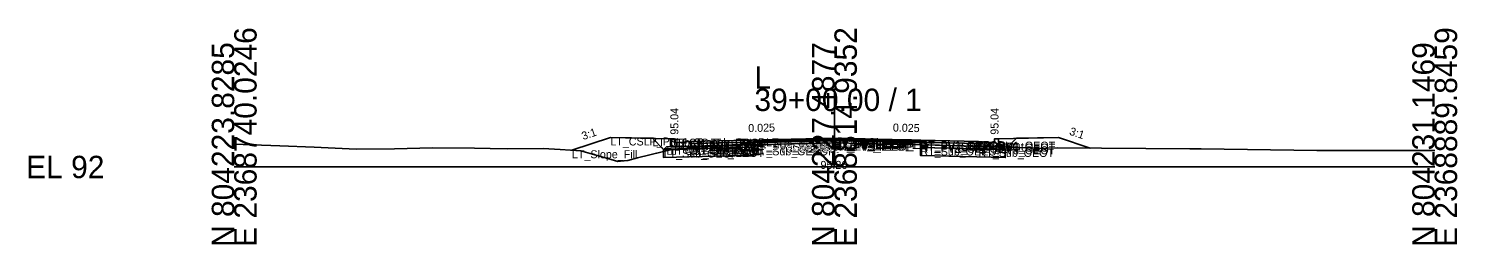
# Model space of a CAD drawing. Extents: x -26 to 8153, y -10 to 9520.
# Drawn here: x 2974.3 to 3152.8, y 5990.3 to 6017.3 of the extents above; entities that cross this region are included whole.
import ezdxf

# ---------------------------------------------------------------- set-up
doc = ezdxf.new("R2010")
doc.units = 0
for name, color, linetype in [('Exist CMT Pavement', 7, 'Continuous'), ('Exist Cross Section Cell', 7, 'Continuous'), ('Exist XS Center Line Elevation Label', 7, 'Continuous'), ('Exist XS Ground Line', 7, 'Continuous'), ('Prop CMT Conc Surface', 7, 'Continuous'), ('Prop CMT Concrete Structures', 7, 'Continuous'), ('Prop CMT Pvmt Course 1', 7, 'Continuous'), ('Prop CMT Pvmt Course 1 CG', 7, 'Continuous'), ('Prop CMT Pvmt Course 1 Wedge', 7, 'Continuous'), ('Prop CMT Pvmt Course 2', 7, 'Continuous'), ('Prop CMT Pvmt Course 2 Wedge', 7, 'Continuous'), ('Prop CMT Pvmt Course 3', 7, 'Continuous'), ('Prop CMT Pvmt Course 3 Wedge', 7, 'Continuous'), ('Prop CMT Pvmt Surface', 7, 'Continuous'), ('Prop CMT Pvmt Wedge Surface 1', 7, 'Continuous'), ('Prop CMT Pvmt Wedge Surface 2', 7, 'Continuous'), ('Prop CMT Pvmt Wedge Surface 3', 7, 'Continuous'), ('Prop CMT Shallow Undercut', 7, 'Continuous'), ('Prop CMT Shallow Undercut Boundary', 7, 'Continuous'), ('Prop CMT Slope Grass', 7, 'Continuous'), ('Prop CMT Subgrade Earthwork', 7, 'Continuous'), ('Prop XS Earthwork Shape', 7, 'Continuous'), ('Prop XS Hydro Elevations', 7, 'Continuous'), ('Prop XS SE Text', 7, 'Continuous'), ('Prop XS Side Slope Text', 7, 'Continuous'), ('Prop XS Subgrade Earthwork', 7, 'Continuous'), ('Scratch_Level_2', 7, 'Continuous'), ('Scratch_Level_6', 7, 'Continuous')]:
    doc.layers.add(name, color=color, linetype=linetype)

msp = doc.modelspace()

# ---------------------------------------------------------------- linework, layer by layer
at = {"layer": 'Exist CMT Pavement'}
for p, q in [((3064.93, 6003.03), (3072.24, 6003.21)), ((3072.24, 6003.21), (3075.1, 6003.27)), ((3075.1, 6003.27), (3078.21, 6003.24)), ((3078.21, 6003.24), (3085.75, 6003.04))]:
    msp.add_line(p, q, dxfattribs=at)
at = {"layer": 'Exist Cross Section Cell'}
for p, q in [((3075, 6000), (3075, 6009.8)), ((3000, 6000), (3075, 6000)), ((3075, 6000), (3150, 6000))]:
    msp.add_line(p, q, dxfattribs=at)
at = {"layer": 'Exist XS Ground Line'}
for p, q in [((3000, 6002.85), (3005.7, 6002.66)), ((3005.7, 6002.66), (3010.01, 6002.46)), ((3010.01, 6002.46), (3015.25, 6002.24)), ((3015.25, 6002.24), (3020.02, 6002.27)), ((3020.02, 6002.27), (3024.79, 6002.39)), ((3024.79, 6002.39), (3030.03, 6002.34)), ((3030.03, 6002.34), (3031.98, 6002.31)), ((3031.98, 6002.31), (3034.18, 6002.28)), ((3034.18, 6002.28), (3038.62, 6002.31)), ((3038.62, 6002.31), (3040.71, 6002.2)), ((3054.83, 6002.24), (3057.97, 6002.46)), ((3057.97, 6002.46), (3062.31, 6002.78)), ((3062.31, 6002.78), (3064.93, 6003.03)), ((3064.93, 6003.03), (3072.24, 6003.21)), ((3072.24, 6003.21), (3075.1, 6003.27)), ((3075.1, 6003.27), (3078.21, 6003.24)), ((3078.21, 6003.24), (3085.75, 6003.04)), ((3085.75, 6003.04), (3086.19, 6002.99)), ((3086.19, 6002.99), (3086.75, 6002.76)), ((3086.75, 6002.76), (3093.67, 6002.57)), ((3093.67, 6002.57), (3099.61, 6002.38)), ((3099.61, 6002.38), (3100.19, 6002.32)), ((3100.19, 6002.32), (3102.89, 6002.4)), ((3102.89, 6002.4), (3119.41, 6002.29)), ((3119.41, 6002.29), (3120.84, 6002.29)), ((3120.84, 6002.29), (3135.29, 6002.05)), ((3040.71, 6002.2), (3043.3, 6002.02)), ((3043.3, 6002.02), (3047.12, 6000.95)), ((3047.12, 6000.95), (3047.94, 6000.7)), ((3047.94, 6000.7), (3048.27, 6000.73)), ((3048.27, 6000.73), (3049.19, 6000.83)), ((3049.19, 6000.83), (3050.41, 6001.15)), ((3050.41, 6001.15), (3054.83, 6002.24)), ((3135.29, 6002.05), (3147.35, 6002.08)), ((3147.35, 6002.08), (3150, 6002.06))]:
    msp.add_line(p, q, dxfattribs=at)
at = {"layer": 'Prop CMT Conc Surface'}
for points in [[(3055, 6003.04), (3055, 6003.54), (3054.5, 6003.54)], [(3057, 6003.17), (3055, 6003.04)], [(3093, 6003.17), (3095, 6003.04)], [(3095, 6003.04), (3095, 6003.54), (3095.5, 6003.54)]]:
    msp.add_lwpolyline(points, dxfattribs=at)
at = {"layer": 'Prop CMT Concrete Structures'}
for points in [[(3057, 6003.17), (3055, 6003.04), (3055, 6003.54), (3054.5, 6003.54)], [(3054.5, 6003.54), (3054.5, 6002.53), (3057, 6002.59)], [(3057, 6002.59), (3057, 6003.17)], [(3093, 6003.17), (3095, 6003.04), (3095, 6003.54), (3095.5, 6003.54)], [(3095.5, 6003.54), (3095.5, 6002.53), (3093, 6002.59)], [(3093, 6002.59), (3093, 6003.17)]]:
    msp.add_lwpolyline(points, dxfattribs=at)
at = {"layer": 'Prop CMT Pvmt Course 1'}
for points in [[(3075, 6003.62), (3057, 6003.17)], [(3057, 6003.17), (3057, 6002.92)], [(3057, 6002.92), (3064.93, 6003.12)], [(3064.93, 6003.25), (3075, 6003.5)], [(3064.93, 6003.12), (3064.93, 6003.25)], [(3075, 6003.37), (3075, 6003.62)], [(3075, 6003.62), (3093, 6003.17)], [(3075, 6003.37), (3075, 6003.62)], [(3075, 6003.5), (3075, 6003.37), (3075, 6003.37)], [(3085.75, 6003.23), (3075, 6003.5)], [(3075, 6003.5), (3075, 6003.37), (3075, 6003.37)], [(3085.75, 6003.11), (3085.75, 6003.23)], [(3093, 6002.92), (3085.75, 6003.11)], [(3093, 6003.17), (3093, 6002.92)], [(3093, 6003.17), (3093, 6002.92)]]:
    msp.add_lwpolyline(points, dxfattribs=at)
at = {"layer": 'Prop CMT Pvmt Course 1 CG'}
for points in [[(3057, 6002.59), (3054, 6002.52), (3053.66, 6002.18)], [(3057, 6002.26), (3057, 6002.59)], [(3093, 6002.59), (3096, 6002.52), (3096.34, 6002.18)], [(3093, 6002.26), (3093, 6002.59)], [(3053.66, 6002.18), (3057, 6002.26)], [(3096.34, 6002.18), (3093, 6002.26)]]:
    msp.add_lwpolyline(points, dxfattribs=at)
at = {"layer": 'Prop CMT Pvmt Course 1 Wedge'}
for points in [[(3075, 6003.5), (3064.93, 6003.25)], [(3075, 6003.5), (3085.75, 6003.23)]]:
    msp.add_lwpolyline(points, dxfattribs=at)
at = {"layer": 'Prop CMT Pvmt Course 2'}
for points in [[(3064.93, 6003.12), (3057, 6002.92)], [(3057, 6002.92), (3057, 6002.59)], [(3057, 6002.59), (3064.93, 6002.79)], [(3064.93, 6002.79), (3064.93, 6003.12)], [(3085.75, 6002.78), (3085.75, 6003.11)], [(3085.75, 6003.11), (3093, 6002.92)], [(3093, 6002.59), (3085.75, 6002.78)], [(3093, 6002.92), (3093, 6002.59)], [(3093, 6002.92), (3093, 6002.59)]]:
    msp.add_lwpolyline(points, dxfattribs=at)
at = {"layer": 'Prop CMT Pvmt Course 2 Wedge'}
for points in [[(3075, 6003.37), (3064.93, 6003.12)], [(3075, 6003.37), (3085.75, 6003.11)]]:
    msp.add_lwpolyline(points, dxfattribs=at)
at = {"layer": 'Prop CMT Pvmt Course 3'}
for points in [[(3064.93, 6002.79), (3057, 6002.59)], [(3057, 6002.59), (3057, 6002.26)], [(3057, 6002.26), (3064.93, 6002.46)], [(3064.93, 6002.46), (3064.93, 6002.79)], [(3085.75, 6002.78), (3093, 6002.59)], [(3085.75, 6002.44), (3085.75, 6002.78)], [(3093, 6002.26), (3085.75, 6002.44)], [(3093, 6002.59), (3093, 6002.26)], [(3093, 6002.59), (3093, 6002.26)]]:
    msp.add_lwpolyline(points, dxfattribs=at)
at = {"layer": 'Prop CMT Pvmt Course 3 Wedge'}
for points in [[(3075, 6003.04), (3064.93, 6002.79)], [(3075, 6003.04), (3085.75, 6002.78)]]:
    msp.add_lwpolyline(points, dxfattribs=at)
at = {"layer": 'Prop CMT Pvmt Surface'}
for points in [[(3075, 6003.62), (3057, 6003.17)], [(3075, 6003.62), (3093, 6003.17)]]:
    msp.add_lwpolyline(points, dxfattribs=at)
at = {"layer": 'Prop CMT Pvmt Wedge Surface 1'}
for points in [[(3057, 6002.92), (3057, 6003.17)], [(3064.93, 6003.12), (3057, 6002.92)], [(3075, 6003.5), (3064.93, 6003.25)], [(3064.93, 6003.25), (3064.93, 6003.12)], [(3075, 6003.5), (3085.75, 6003.23)], [(3085.75, 6003.23), (3085.75, 6003.11)], [(3085.75, 6003.11), (3093, 6002.92)], [(3093, 6002.92), (3093, 6003.17)], [(3093, 6002.92), (3093, 6003.17)]]:
    msp.add_lwpolyline(points, dxfattribs=at)
at = {"layer": 'Prop CMT Pvmt Wedge Surface 2'}
for points in [[(3075, 6003.37), (3057, 6002.92)], [(3057, 6002.92), (3057, 6003.17)], [(3075, 6003.37), (3093, 6002.92)], [(3093, 6002.92), (3093, 6003.17)], [(3093, 6002.92), (3093, 6003.17)]]:
    msp.add_lwpolyline(points, dxfattribs=at)
at = {"layer": 'Prop CMT Pvmt Wedge Surface 3'}
for points in [[(3057, 6002.59), (3057, 6003.17)], [(3075, 6003.04), (3057, 6002.59)], [(3075, 6003.04), (3093, 6002.59)], [(3093, 6002.59), (3093, 6003.17)], [(3093, 6002.59), (3093, 6003.17)]]:
    msp.add_lwpolyline(points, dxfattribs=at)
at = {"layer": 'Prop CMT Shallow Undercut'}
for p, q in [((3096.34, 6002.18), (3085.75, 6002.44)), ((3085.75, 6002.44), (3085.75, 6001.44)), ((3085.75, 6001.44), (3096.34, 6001.18)), ((3096.34, 6001.18), (3096.34, 6002.18))]:
    msp.add_line(p, q, dxfattribs=at)
msp.add_lwpolyline([(3053.66, 6001.95), (3054.7, 6002.2), (3064.93, 6002.46), (3064.93, 6001.46), (3053.66, 6001.18)], close=True, dxfattribs=at)
at = {"layer": 'Prop CMT Shallow Undercut Boundary'}
for p, q in [((3064.93, 6002.46), (3064.93, 6001.46)), ((3085.75, 6002.44), (3085.75, 6001.44)), ((3053.66, 6002.18), (3053.66, 6001.18)), ((3053.66, 6001.18), (3064.93, 6001.46)), ((3085.75, 6001.44), (3096.34, 6001.18)), ((3096.34, 6002.18), (3096.34, 6001.18))]:
    msp.add_line(p, q, dxfattribs=at)
at = {"layer": 'Prop CMT Slope Grass'}
for points in [[(3054.5, 6003.54), (3047, 6003.69), (3042.2, 6002.09)], [(3095.5, 6003.54), (3103, 6003.69), (3106.96, 6002.37)]]:
    msp.add_lwpolyline(points, dxfattribs=at)
at = {"layer": 'Prop CMT Subgrade Earthwork'}
for points in [[(3057, 6002.26), (3053.66, 6002.18), (3052.25, 6003.59)], [(3064.93, 6002.46), (3057, 6002.26)], [(3064.93, 6002.46), (3064.95, 6003.03)], [(3085.75, 6002.44), (3085.73, 6003.05)], [(3085.75, 6002.44), (3093, 6002.26)], [(3093, 6002.26), (3096.34, 6002.18), (3097.75, 6003.59)]]:
    msp.add_lwpolyline(points, dxfattribs=at)
at = {"layer": 'Prop XS Earthwork Shape'}
for points in [[(3043.3, 6002.02), (3047.12, 6000.95), (3047.94, 6000.7), (3048.27, 6000.73), (3049.19, 6000.83), (3050.41, 6001.15), (3053.66, 6001.95), (3053.66, 6002.18), (3052.25, 6003.59), (3047, 6003.69), (3042.2, 6002.09)], [(3057, 6002.26), (3054.7, 6002.2), (3053.66, 6001.95), (3053.66, 6001.18), (3064.93, 6001.46), (3064.93, 6002.46)], [(3064.93, 6002.46), (3064.95, 6003.03), (3064.93, 6003.03), (3062.31, 6002.78), (3057.97, 6002.46), (3054.83, 6002.24), (3054.7, 6002.2), (3057, 6002.26)], [(3085.75, 6003.04), (3086.19, 6002.99), (3086.75, 6002.76), (3093.67, 6002.57), (3096.64, 6002.48), (3096.34, 6002.18), (3093, 6002.26), (3085.75, 6002.44), (3085.73, 6003.05)], [(3093, 6002.26), (3096.34, 6002.18), (3096.34, 6001.18), (3085.75, 6001.44), (3085.75, 6002.44)], [(3097.75, 6003.59), (3103, 6003.69), (3106.96, 6002.37), (3102.89, 6002.4), (3100.19, 6002.32), (3099.61, 6002.38), (3096.64, 6002.48)], [(3053.66, 6002.18), (3053.66, 6001.95), (3054.7, 6002.2)]]:
    msp.add_lwpolyline(points, close=True, dxfattribs=at)
at = {"layer": 'Prop XS Subgrade Earthwork'}
for p, q in [((3053.66, 6002.18), (3064.93, 6002.46)), ((3096.34, 6002.18), (3085.75, 6002.44))]:
    msp.add_line(p, q, dxfattribs=at)
at = {"layer": 'Scratch_Level_6'}
for p, q in [((3096.34, 6002.18), (3085.75, 6002.44)), ((3085.75, 6002.44), (3085.75, 6001.44)), ((3085.75, 6001.44), (3096.34, 6001.18)), ((3096.34, 6001.18), (3096.34, 6002.18))]:
    msp.add_line(p, q, dxfattribs=at)
msp.add_lwpolyline([(3053.66, 6001.95), (3054.7, 6002.2), (3064.93, 6002.46), (3064.93, 6001.46), (3053.66, 6001.18)], close=True, dxfattribs=at)

# ---------------------------------------------------------------- texts
at = {"layer": 'Exist Cross Section Cell'}
for s, p in [('E 2368740.0246', (3002.8, 5990)), ('E 2368814.9352', (3077.8, 5990)), ('E 2368889.8459', (3152.8, 5990)), ('N 804223.8285', (3000, 5990)), ('N 804227.4877', (3075, 5990)), ('N 804231.1469', (3150, 5990))]:
    msp.add_text(s, height=2.8, rotation=90, dxfattribs=at).set_placement(p)
for s, p in [('L', (3065, 6009.8)), ('39+00.00 / 1', (3065, 6007)), ('EL 92', (2974, 5998.6))]:
    msp.add_text(s, height=2.8, dxfattribs=at).set_placement(p)
at = {"layer": 'Exist XS Center Line Elevation Label'}
msp.add_text('95.26', height=1, dxfattribs=at).set_placement((3073.26, 5999.76))
at = {"layer": 'Prop XS Hydro Elevations'}
for p in [(3055.5, 6004.04), (3095.5, 6004.04)]:
    msp.add_text('95.04', height=1, rotation=90, dxfattribs=at).set_placement(p)
at = {"layer": 'Prop XS SE Text'}
for rotation, p in [(1.4321, (3064.24, 6004.36)), (358.5679, (3082.29, 6004.44))]:
    msp.add_text('0.025', height=1, rotation=rotation, dxfattribs=at).set_placement(p)
at = {"layer": 'Prop XS Side Slope Text'}
for rotation, p in [(18.4349, (3043.61, 6003.36)), (341.5651, (3104.28, 6004.06))]:
    msp.add_text('3:1', height=1, rotation=rotation, dxfattribs=at).set_placement(p)
at = {"layer": 'Scratch_Level_2'}
for s, p in [('LT_CSLP_Pnt', (3047, 6002.69)), ('LT_Sub_Trench_Out_DLT', (3052.25, 6002.59)), ('LT_CG1_Shelf_Out', (3054, 6001.52)), ('LT_CG_Top_BOC', (3054.5, 6002.54)), ('LT_CG_Bot_BOC', (3054.5, 6001.53)), ('LT_CG_Top_Face', (3055, 6002.54)), ('LT_CG_Top_Gut', (3055, 6002.04)), ('LT_PV1_OEOT', (3057, 6002.17)), ('LT_PV2_OEOT', (3057, 6001.92)), ('LT_PV3_OEOT', (3057, 6001.59)), ('LT_CG_Bot_IE', (3057, 6001.59)), ('LT_Sub_OEOT', (3057, 6001.26)), ('LT_PV1_OEEOP', (3064.93, 6002.25)), ('LT_PV2_OEEOP', (3064.93, 6002.12)), ('LT_PV_OEEOP_EG', (3064.93, 6002.03)), ('LT_PV3_OEEOP', (3064.93, 6001.79)), ('LT_Sub_OEEOP', (3064.93, 6001.46)), ('LT_PV_Sub_Tie_Out', (3064.95, 6002.03)), ('PV1_PGL', (3075, 6002.62)), ('RT_PV1_IEEOP', (3075, 6002.5)), ('LT_PV1_IEEOP', (3075, 6002.5)), ('RT_PV2_IEEOP', (3075, 6002.37)), ('LT_PV2_IEEOP', (3075, 6002.37)), ('PV2_PGL', (3075, 6002.37)), ('RT_PV_IEEOP_EG', (3075, 6002.26)), ('LT_PV_IEEOP_EG', (3075, 6002.26)), ('RT_PV3_IEEOP', (3075, 6002.04)), ('LT_PV3_IEEOP', (3075, 6002.04)), ('RT_PV_Sub_Tie_Out', (3085.73, 6002.05)), ('RT_PV1_OEEOP', (3085.75, 6002.23)), ('RT_PV2_OEEOP', (3085.75, 6002.11)), ('RT_PV_OEEOP_EG', (3085.75, 6002.04)), ('RT_PV3_OEEOP', (3085.75, 6001.78)), ('RT_Sub_OEEOP', (3085.75, 6001.44)), ('RT_PV1_OEOT', (3093, 6002.17)), ('RT_PV2_OEOT', (3093, 6001.92)), ('RT_PV3_OEOT', (3093, 6001.59)), ('RT_Sub_OEOT', (3093, 6001.26)), ('LT_Slope_Fill', (3042.2, 6001.09)), ('LT_Sub_OEOP', (3053.66, 6001.18))]:
    msp.add_text(s, height=1, dxfattribs=at).set_placement(p)

doc.saveas('drawing.dxf')
